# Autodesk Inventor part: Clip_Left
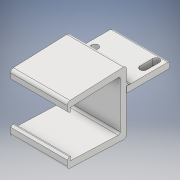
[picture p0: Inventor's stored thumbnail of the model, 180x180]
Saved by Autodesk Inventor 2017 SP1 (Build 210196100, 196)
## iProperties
Created: 2017-10
Part Number: Clip_Left
Material: ABS Plastic
Document SubType Name: Modeling
Designer: Nick
Density: 1.06 g/cm^3
Appearance: Smooth - White
Part Number: Clip_Left_3DPrint
Material: Generic
Density: 1 g/cm^3
Appearance: Default
Author: Nick
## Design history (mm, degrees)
sketch "Sketch1"
  geometry: L1 (0, 0)-(0, -16.128); L2 (-3.2, 0)-(-3.2, -12.8); L3 (-30.404, -14.939)-(0, -16.128); L4 (-3.2, 0)-(0, 0); L5 (-30.404, -14.939)-(-30.201, -9.743); L6 (-30.201, -9.743)-(-28.702, -9.802); L7 (-28.78, -11.8)-(-28.702, -9.802); L8 (-3.2, -12.8)-(-28.78, -11.8); 3 further points; 1 other entity
  constraints: 16 end point, 3 perpendicular, 2 coincident, 1 horizontal, 1 parallel, 1 vertical, 2 other
  dimensions: "d0" = 3.2 distance between parallel lines of L1 L2; "d6" = 12.8 distance of L2.start L2.end; "d7" = 2 distance of L7.start L6.end; "d8" = 25.6 distance of L7.start L2.end (= 2 x d6); "d9" = 1.5 distance of L5.end L6.end; "d13" = 3.2 distance between parallel lines of L3 L8; "d14" = 1 vertical distance of L7.start L2.end; "d20" = 87.7613 deg angle of L3 L1 (derived)
extrude "Clamp half" new body sketch "Sketch1" distance "d10" = 29; taper "d11" = 0 deg
mirror "Clamp Mirror"
workplane "Work Plane1"
sketch "Sketch2"
  geometry: L1 (29.1, 22)-(-0.1, 22); L2 (-0.1, 22)-(-0.1, 0); L3 (-0.1, 0)-(29.1, 0); L4 (29.1, 0)-(29.1, 22); L5 (0, 0)-(29, 0) reference; L6 (27.1, 20.5)-(23.6, 20.5); L7 (23.6, 20.5)-(23.6, 18.75); L8 (23.6, 10.5)-(27.1, 10.5); L9 (27.1, 10.5)-(27.1, 12.25); L10 (27.1, 18.75)-(27.1, 20.5); L11 (23.6, 18.75)-(23.6, 12.25); L12 (23.6, 12.25)-(23.6, 10.5); L13 (27.1, 12.25)-(27.1, 18.75); L14 (14.5, 22)-(14.5, 0); L15 (1.9, 1)-(1.9, 2.75); L16 (1.9, 2.75)-(1.9, 9.25); L17 (1.9, 9.25)-(1.9, 11); L18 (5.4, 2.75)-(5.4, 1); L19 (5.4, 11)-(5.4, 9.25); L20 (5.4, 9.25)-(5.4, 2.75); A1 r 1.75 centre (25.35, 18.75) between (27.1, 18.75) and (23.6, 18.75); A2 r 1.75 centre (25.35, 12.25) between (23.6, 12.25) and (27.1, 12.25); A3 r 1.75 centre (3.65, 2.75) between (1.9, 2.75) and (5.4, 2.75); A4 r 1.75 centre (3.65, 9.25) between (5.4, 9.25) and (1.9, 9.25); 6 further points; 2 other entities
  constraints: 38 end point, 22 point on circle, 13 parallel, 6 vertical, 4 centre point, 4 horizontal alignment, 4 midpoint, 4 perpendicular, 4 point on line, 2 horizontal, 1 tangent, 1 vertical alignment, 8 other
  dimensions: "d16" = 29.2 distance of L1.start L1.end; "d17" = 22 distance of L3.end L1.start; "d21" = 3.5 distance of L6.start L6.end; "d22" = 10 distance of L6.end L8.start; "d23" = 1.75 radius of A1 (= 0.5 x d21); "d24" = 2 distance between parallel lines of L4 L9; "d25" = 1.5 distance from line of L1 L6.start; "d26" = 1.75 radius of A2 (= d23); "d27" = 18.2 distance between parallel lines of L11 L20; "d30" = 1.75 radius of A4 (= d23); "d31" = 1.75 radius of A3 (= d23); "d34" = 3.5 distance of L16.end L19.end (= d21); "d36" = 11 distance from line of L1 L17.end
extrude "Extrusion4" join sketch "Sketch2" distance "d28" = 3.2; taper "d29" = 0 deg
fillet "Fillet1" dims "d37" = 2
fillet "Fillet2" dims "d38" = 1.5
fillet "Fillet3" dims "d39" = 1
chamfer "Chamfer1" distance "d40" = 1; stored, may be unused: second distance "d41" = 2, angle "d42" = 45 deg
fillet "Fillet4" dims "d43" = 1
body "Solid2"
other parameters: "d15" = 7, "sa_0" = 0, "sa_1" = -781.25, "sa_2" = 19984.73539, "sa_3" = 0, "sa_4" = 0, "sa_5" = 50000
